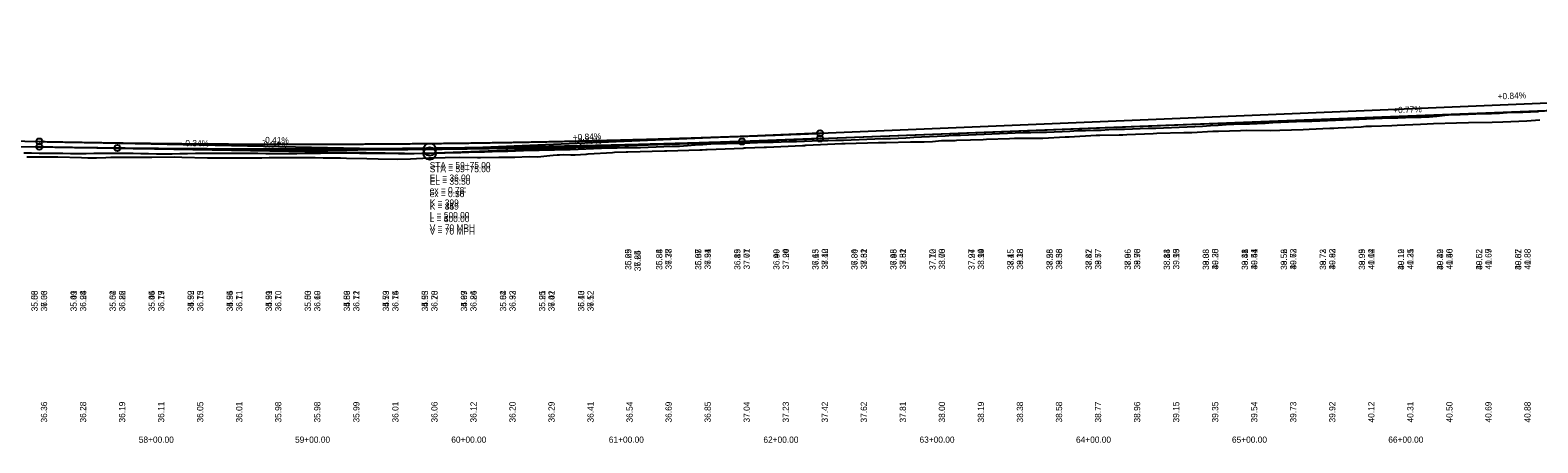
# Model space of a CAD drawing. Extents: x 3880794 to 3915434, y 287517 to 300173.
# Drawn here: x 3886257 to 3887223, y 296520 to 296784 of the extents above; entities that cross this region are included whole.
import ezdxf

# ---------------------------------------------------------------- set-up
doc = ezdxf.new("R2010")
doc.units = 0
for name, color, linetype in [('Level 1', 7, 'Continuous'), ('Level 2', 7, 'Continuous'), ('Level 30', 7, 'Continuous'), ('Level 31', 7, 'Continuous'), ('Level 32', 7, 'Continuous')]:
    doc.layers.add(name, color=color, linetype=linetype)

msp = doc.modelspace()

# ---------------------------------------------------------------- linework, layer by layer
at = {"layer": 'Level 1'}
for p, q in [((3886713.3, 296712.95), (3887288.3, 296735.06)), ((3886763.3, 296714.87), (3887238.3, 296733.14)), ((3885988.3, 296714.31), (3886263.3, 296709.57)), ((3886763.3, 296714.87), (3886517.29, 296705.41)), ((3886038.3, 296713.45), (3886313.3, 296708.71)), ((3886263.3, 296709.57), (3886509.3, 296705.33)), ((3886313.3, 296708.71), (3886509.3, 296705.33)), ((3886713.3, 296712.95), (3886517.29, 296705.41))]:
    msp.add_line(p, q, dxfattribs=at)
for points in [[(3886777.28, 296711.61), (3886777.93, 296711.63), (3886778.65, 296711.66), (3886779.46, 296711.74), (3886800.69, 296712.3), (3886801.5, 296712.33), (3886802.48, 296712.28), (3886803.73, 296712.3), (3886805.53, 296712.37), (3886821.22, 296712.7), (3886822.8, 296712.82), (3886825.32, 296712.79), (3886829.99, 296712.71), (3886835.19, 296712.96), (3886841.06, 296713.51), (3886849.7, 296713.65), (3886850.95, 296713.71), (3886859.58, 296713.97), (3886867.68, 296714.27), (3886869.92, 296714.35), (3886884.64, 296714.91), (3886887.72, 296715.02), (3886903.31, 296715.07), (3886905.9, 296715.12), (3886920.29, 296715.88), (3886922.81, 296715.99), (3886940.16, 296716.94), (3886942.47, 296717.06), (3886954.89, 296717.13), (3886957.16, 296717.29), (3886959.74, 296717.38), (3886976.66, 296718.15), (3886979.02, 296718.21), (3886996.27, 296718.61), (3886998.79, 296718.68), (3887001.42, 296718.78), (3887014.73, 296719.51), (3887018.4, 296719.56), (3887032.54, 296720.08), (3887036.17, 296720.18), (3887052.03, 296720.02), (3887057.62, 296720.16), (3887072.72, 296720.7), (3887076.51, 296720.83), (3887089.83, 296721.4), (3887092.35, 296721.47), (3887095.17, 296721.64), (3887109.82, 296722.45), (3887112.73, 296722.67), (3887116.46, 296722.73), (3887129.49, 296723.14), (3887132.79, 296723.46), (3887147.82, 296724.16), (3887151.97, 296724.25), (3887156.13, 296724.44), (3887170.81, 296724.98), (3887178.64, 296725.16), (3887193.73, 296725.44), (3887200.58, 296725.6), (3887215.89, 296726.2), (3887224.27, 296726.73)], [(3886255.33, 296703.2), (3886270.26, 296703.12), (3886275.11, 296703.11), (3886290.35, 296702.76), (3886294.42, 296702.54), (3886299.85, 296702.56), (3886305.8, 296702.58), (3886309.07, 296702.85), (3886325.47, 296702.92), (3886329.92, 296702.94), (3886335.28, 296702.94), (3886349.68, 296703.08), (3886354.67, 296702.88), (3886370.93, 296702.55), (3886374.88, 296702.38), (3886379.51, 296702.37), (3886385.58, 296702.39), (3886390.44, 296702.49), (3886405.74, 296702.53), (3886410.39, 296702.7), (3886415.81, 296702.69), (3886427.73, 296702.71), (3886429.52, 296702.73), (3886431.64, 296702.75), (3886440.03, 296702.76), (3886444.98, 296702.42), (3886456.07, 296702.48), (3886459.94, 296702.29), (3886472.94, 296701.96), (3886480.39, 296701.79), (3886492.93, 296701.69), (3886501.1, 296701.92), (3886512.68, 296702.37), (3886513.02, 296702.38), (3886523.13, 296702.71), (3886532.15, 296702.84), (3886543.81, 296702.62), (3886545.77, 296702.66), (3886557.62, 296702.96), (3886566.49, 296702.98), (3886567.81, 296702.98), (3886576.92, 296703.22), (3886582.57, 296703.2), (3886590.24, 296704.03), (3886592.33, 296704.23), (3886594.83, 296704.37), (3886596.34, 296704.45), (3886598.67, 296704.51), (3886603.66, 296704.35), (3886605.48, 296704.39), (3886606.51, 296704.46), (3886613.27, 296704.89), (3886613.64, 296704.92), (3886614.88, 296705.04), (3886630.41, 296705.95), (3886631.54, 296706), (3886639.06, 296706.24), (3886640.13, 296706.22), (3886663.57, 296706.99), (3886664.11, 296706.98), (3886664.61, 296706.98), (3886665.13, 296706.99), (3886686.28, 296707.62), (3886686.86, 296707.62), (3886687.68, 296707.63), (3886690.2, 296707.74), (3886691.01, 296707.78), (3886713.97, 296708.73), (3886714.72, 296708.79), (3886715.56, 296708.82), (3886727.4, 296709.35), (3886728.22, 296709.37), (3886729.06, 296709.36), (3886752.07, 296710.41), (3886752.6, 296710.44), (3886753.28, 296710.47), (3886753.85, 296710.5), (3886754.46, 296710.5), (3886777.28, 296711.61)]]:
    msp.add_lwpolyline(points, dxfattribs=at)
msp.add_circle((3886513.3, 296705.26), 4, dxfattribs=at)
msp.add_circle((3886513.3, 296705.26), 4, dxfattribs=at)
for points in [[(3886263.3, 296709.57), (3886273.3, 296709.4), (3886283.3, 296709.24), (3886293.3, 296709.1), (3886303.3, 296708.97), (3886313.3, 296708.84), (3886323.3, 296708.73), (3886333.3, 296708.63), (3886343.3, 296708.54), (3886353.3, 296708.47), (3886363.3, 296708.4), (3886373.3, 296708.34), (3886383.3, 296708.3), (3886393.3, 296708.27), (3886403.3, 296708.25), (3886413.3, 296708.23), (3886423.3, 296708.23), (3886433.3, 296708.25), (3886443.3, 296708.27), (3886453.3, 296708.3), (3886463.3, 296708.35), (3886473.3, 296708.4), (3886483.3, 296708.47), (3886493.3, 296708.55), (3886503.3, 296708.64), (3886513.3, 296708.74), (3886523.3, 296708.85), (3886533.3, 296708.97), (3886543.3, 296709.11), (3886553.3, 296709.25), (3886563.3, 296709.41), (3886573.3, 296709.58), (3886583.3, 296709.75), (3886593.3, 296709.94), (3886603.3, 296710.14), (3886613.3, 296710.36), (3886623.3, 296710.58), (3886633.3, 296710.81), (3886643.3, 296711.06), (3886653.3, 296711.32), (3886663.3, 296711.58), (3886673.3, 296711.86), (3886683.3, 296712.15), (3886693.3, 296712.45), (3886703.3, 296712.77), (3886713.3, 296713.09), (3886723.3, 296713.42), (3886733.3, 296713.77), (3886743.3, 296714.13), (3886753.3, 296714.49), (3886763.3, 296714.87)], [(3886313.3, 296708.71), (3886321.3, 296708.57), (3886329.3, 296708.45), (3886337.3, 296708.33), (3886345.3, 296708.22), (3886353.3, 296708.13), (3886361.3, 296708.04), (3886369.3, 296707.96), (3886377.3, 296707.89), (3886385.3, 296707.82), (3886393.3, 296707.77), (3886401.3, 296707.73), (3886409.3, 296707.69), (3886417.3, 296707.67), (3886425.3, 296707.65), (3886433.3, 296707.64), (3886441.3, 296707.64), (3886449.3, 296707.65), (3886457.3, 296707.67), (3886465.3, 296707.69), (3886473.3, 296707.73), (3886481.3, 296707.77), (3886489.3, 296707.83), (3886497.3, 296707.89), (3886505.3, 296707.96), (3886513.3, 296708.04), (3886521.3, 296708.13), (3886529.3, 296708.23), (3886537.3, 296708.34), (3886545.3, 296708.45), (3886553.3, 296708.58), (3886561.3, 296708.71), (3886569.3, 296708.85), (3886577.3, 296709.01), (3886585.3, 296709.17), (3886593.3, 296709.34), (3886601.3, 296709.52), (3886609.3, 296709.7), (3886617.3, 296709.9), (3886625.3, 296710.1), (3886633.3, 296710.32), (3886641.3, 296710.54), (3886649.3, 296710.77), (3886657.3, 296711.01), (3886665.3, 296711.26), (3886673.3, 296711.52), (3886681.3, 296711.79), (3886689.3, 296712.07), (3886697.3, 296712.35), (3886705.3, 296712.65), (3886713.3, 296712.95)]]:
    msp.add_spline(points, degree=3, dxfattribs=at)
at = {"layer": 'Level 2'}
for p, q in [((3886763.3, 296718.25), (3888338.3, 296784.36)), ((3885988.3, 296718.62), (3886263.3, 296712.93)), ((3886763.3, 296718.25), (3886517.29, 296707.92)), ((3886263.3, 296712.93), (3886509.3, 296707.84))]:
    msp.add_line(p, q, dxfattribs=at)
for points in [[(3886538.3, 296706.11), (3886543.3, 296706.24), (3886548.3, 296706.36), (3886553.3, 296706.49), (3886558.3, 296706.68), (3886563.3, 296706.84), (3886568.3, 296707.01), (3886573.3, 296707.18), (3886578.3, 296707.35), (3886583.3, 296707.4), (3886588.3, 296707.52), (3886593.3, 296707.65), (3886598.3, 296707.78), (3886603.3, 296707.91), (3886608.3, 296708.06), (3886613.3, 296708.26), (3886618.3, 296708.46), (3886623.3, 296708.66), (3886628.3, 296708.85), (3886633.3, 296708.94), (3886638.3, 296709.03), (3886643.3, 296709.11), (3886648.3, 296709.2), (3886653.3, 296709.29), (3886658.3, 296709.48), (3886663.3, 296709.67), (3886668.3, 296709.89), (3886673.3, 296709.87), (3886678.3, 296710.36), (3886683.3, 296710.79), (3886688.3, 296711.12), (3886693.3, 296711.47), (3886698.3, 296711.56), (3886703.3, 296711.68), (3886708.3, 296711.87), (3886713.3, 296711.98), (3886718.3, 296712.13), (3886723.3, 296712.3), (3886728.3, 296712.45), (3886733.3, 296712.59), (3886738.3, 296712.71), (3886743.3, 296712.84), (3886748.3, 296713.01), (3886753.3, 296713.19), (3886758.3, 296713.34), (3886763.3, 296713.48), (3886768.3, 296713.63), (3886773.3, 296713.74), (3886778.3, 296713.9), (3886783.3, 296714.09), (3886788.3, 296714.28), (3886793.3, 296714.49), (3886798.3, 296714.69), (3886803.3, 296714.83), (3886808.3, 296714.96), (3886813.3, 296715.16), (3886818.3, 296715.39), (3886823.3, 296715.62), (3886828.3, 296715.84), (3886833.3, 296716.06), (3886838.3, 296716.35), (3886843.3, 296716.63), (3886848.3, 296716.9), (3886853.3, 296717.11), (3886858.3, 296717.29), (3886863.3, 296717.46), (3886868.3, 296717.67), (3886873.3, 296717.9), (3886878.3, 296718.12), (3886883.3, 296718.35), (3886888.3, 296718.5), (3886893.3, 296718.64), (3886898.3, 296718.77), (3886903.3, 296718.88), (3886908.3, 296719), (3886913.3, 296719.13), (3886918.3, 296719.34), (3886923.3, 296719.61), (3886928.3, 296719.89), (3886933.3, 296720.01), (3886938.3, 296720.12), (3886943.3, 296720.29), (3886948.3, 296720.56), (3886953.3, 296720.75), (3886958.3, 296720.91), (3886963.3, 296721.08), (3886968.3, 296721.23), (3886973.3, 296721.39), (3886978.3, 296721.58), (3886983.3, 296721.76), (3886988.3, 296721.95), (3886993.3, 296722.16), (3886998.3, 296722.38), (3887003.3, 296722.6), (3887008.3, 296722.82), (3887013.3, 296723.14), (3887018.3, 296723.46), (3887023.3, 296723.78), (3887028.3, 296724.07), (3887033.3, 296724.18), (3887038.3, 296724.29)], [(3887038.3, 296724.29), (3887043.3, 296724.48), (3887048.3, 296724.7), (3887053.3, 296725.04), (3887058.3, 296725.39), (3887063.3, 296725.54), (3887068.3, 296725.7), (3887073.3, 296725.89), (3887078.3, 296726.07), (3887083.3, 296726.22), (3887088.3, 296726.39), (3887093.3, 296726.57), (3887098.3, 296726.79), (3887103.3, 296727.09), (3887108.3, 296727.3), (3887113.3, 296727.52), (3887118.3, 296727.71), (3887123.3, 296727.86), (3887128.3, 296728.03), (3887133.3, 296728.18), (3887138.3, 296728.38), (3887143.3, 296728.64), (3887148.3, 296728.64), (3887153.3, 296728.81), (3887158.3, 296729.27), (3887163.3, 296729.87), (3887168.3, 296730.17), (3887173.3, 296730.34), (3887178.3, 296730.52), (3887183.3, 296730.69), (3887188.3, 296730.84), (3887193.3, 296731), (3887198.3, 296731.16), (3887203.3, 296731.45), (3887208.3, 296731.65), (3887213.3, 296731.85), (3887218.3, 296732.04), (3887223.3, 296732.23)], [(3886253.3, 296705.64), (3886258.3, 296705.63), (3886263.3, 296705.52), (3886268.3, 296705.45), (3886273.3, 296705.44), (3886278.3, 296705.39), (3886283.3, 296705.26), (3886288.3, 296705.22), (3886293.3, 296705.3), (3886298.3, 296705.38), (3886303.3, 296705.36), (3886308.3, 296705.4), (3886313.3, 296705.45), (3886318.3, 296705.53), (3886323.3, 296705.5), (3886328.3, 296705.33), (3886333.3, 296705.16), (3886338.3, 296705.01), (3886343.3, 296705.05), (3886348.3, 296705.14), (3886353.3, 296705.22), (3886358.3, 296705.29), (3886363.3, 296705.37), (3886368.3, 296705.41), (3886373.3, 296705.46), (3886378.3, 296705.51), (3886383.3, 296705.53), (3886388.3, 296705.49), (3886393.3, 296705.44), (3886398.3, 296705.43), (3886403.3, 296705.4), (3886408.3, 296705.35), (3886413.3, 296705.3), (3886418.3, 296705.25), (3886423.3, 296705.24), (3886428.3, 296705.31), (3886433.3, 296705.39), (3886438.3, 296705.43), (3886443.3, 296705.5), (3886448.3, 296705.58), (3886453.3, 296705.65), (3886458.3, 296705.59), (3886463.3, 296705.58), (3886468.3, 296705.56), (3886473.3, 296705.55), (3886478.3, 296705.47), (3886483.3, 296705.42), (3886488.3, 296705.38), (3886493.3, 296705.35), (3886498.3, 296705.31), (3886503.3, 296705.34), (3886508.3, 296705.43), (3886513.3, 296705.53), (3886518.3, 296705.62), (3886523.3, 296705.71), (3886528.3, 296705.81), (3886533.3, 296705.99), (3886538.3, 296706.11)]]:
    msp.add_lwpolyline(points, dxfattribs=at)
for centre, radius in [((3886263.3, 296712.93), 2), ((3886763.3, 296718.25), 2), ((3886513.3, 296707.76), 4)]:
    msp.add_circle(centre, radius, dxfattribs=at)
msp.add_spline([(3886263.3, 296712.93), (3886273.3, 296712.73), (3886283.3, 296712.54), (3886293.3, 296712.37), (3886303.3, 296712.2), (3886313.3, 296712.05), (3886323.3, 296711.91), (3886333.3, 296711.79), (3886343.3, 296711.68), (3886353.3, 296711.57), (3886363.3, 296711.49), (3886373.3, 296711.41), (3886383.3, 296711.35), (3886393.3, 296711.3), (3886403.3, 296711.26), (3886413.3, 296711.24), (3886423.3, 296711.22), (3886433.3, 296711.22), (3886443.3, 296711.24), (3886453.3, 296711.26), (3886463.3, 296711.3), (3886473.3, 296711.35), (3886483.3, 296711.41), (3886493.3, 296711.49), (3886503.3, 296711.57), (3886513.3, 296711.67), (3886523.3, 296711.79), (3886533.3, 296711.91), (3886543.3, 296712.05), (3886553.3, 296712.2), (3886563.3, 296712.36), (3886573.3, 296712.54), (3886583.3, 296712.73), (3886593.3, 296712.93), (3886603.3, 296713.14), (3886613.3, 296713.36), (3886623.3, 296713.6), (3886633.3, 296713.85), (3886643.3, 296714.12), (3886653.3, 296714.39), (3886663.3, 296714.68), (3886673.3, 296714.98), (3886683.3, 296715.29), (3886693.3, 296715.62), (3886703.3, 296715.96), (3886713.3, 296716.31), (3886723.3, 296716.67), (3886733.3, 296717.05), (3886743.3, 296717.44), (3886753.3, 296717.84), (3886763.3, 296718.25)], degree=3, dxfattribs=at)
at = {"layer": 'Level 31'}
for centre in [(3886713.3, 296712.95), (3886763.3, 296714.87), (3886263.3, 296709.57), (3886313.3, 296708.71)]:
    msp.add_circle(centre, 2, dxfattribs=at)

# ---------------------------------------------------------------- texts
at = {"layer": 'Level 2'}
for s, rotation, p in [('+0.84%', 2.4036, (3887197.28, 296739.86)), ('-0.41%', 358.81474, (3886406.09, 296711.98)), ('+0.84%', 2.4036, (3886604.98, 296713.61)), ('37.25', 90, (3886648.45, 296629.75)), ('37.38', 90, (3886668.3, 296630.87)), ('37.54', 90, (3886693.3, 296630.87)), ('37.71', 90, (3886718.3, 296630.87)), ('37.90', 90, (3886743.3, 296630.87)), ('38.10', 90, (3886768.3, 296630.87)), ('38.31', 90, (3886793.3, 296630.87)), ('38.52', 90, (3886818.3, 296630.87)), ('38.73', 90, (3886843.3, 296630.87)), ('38.94', 90, (3886868.3, 296630.87)), ('39.15', 90, (3886893.3, 296630.87)), ('39.36', 90, (3886918.3, 296630.87)), ('39.57', 90, (3886943.3, 296630.87)), ('39.78', 90, (3886968.3, 296630.87)), ('39.99', 90, (3886993.3, 296630.87)), ('40.20', 90, (3887018.3, 296630.87)), ('40.41', 90, (3887043.3, 296630.87)), ('40.62', 90, (3887068.3, 296630.87)), ('40.83', 90, (3887093.3, 296630.87)), ('41.04', 90, (3887118.3, 296630.87)), ('41.25', 90, (3887143.3, 296630.87)), ('41.46', 90, (3887168.3, 296630.87)), ('41.67', 90, (3887193.3, 296630.87)), ('41.88', 90, (3887218.3, 296630.87)), ('37.03', 90, (3886268.3, 296604.02)), ('36.94', 90, (3886293.3, 296604.02)), ('36.86', 90, (3886318.3, 296604.02)), ('36.79', 90, (3886343.3, 296604.02)), ('36.75', 90, (3886368.3, 296604.02)), ('36.71', 90, (3886393.3, 296604.02)), ('36.70', 90, (3886418.3, 296604.02)), ('36.69', 90, (3886443.3, 296604.02)), ('36.71', 90, (3886468.3, 296604.02)), ('36.74', 90, (3886493.3, 296604.02)), ('36.78', 90, (3886518.3, 296604.02)), ('36.84', 90, (3886543.3, 296604.02)), ('36.92', 90, (3886568.3, 296604.02)), ('37.01', 90, (3886593.3, 296604.02)), ('37.12', 90, (3886618.3, 296604.02))]:
    msp.add_text(s, height=4, rotation=rotation, dxfattribs=at).set_placement(p)
for s, p in [('STA = 59+75.00', (3886513.3, 296695.76)), ('EL = 36.00', (3886513.3, 296687.76)), ("ex = 0.78'", (3886513.3, 296679.76)), ('K = 399', (3886513.3, 296671.76)), ('L = 500.00', (3886513.3, 296663.76)), ('V = 70 MPH', (3886513.3, 296655.76)), ('58+00.00', (3886326.99, 296519.76)), ('59+00.00', (3886427.05, 296519.76)), ('60+00.00', (3886527.12, 296519.76)), ('61+00.00', (3886628, 296519.76)), ('62+00.00', (3886726.99, 296519.76)), ('63+00.00', (3886826.96, 296519.76)), ('64+00.00', (3886927.18, 296519.76)), ('65+00.00', (3887027.05, 296519.76)), ('66+00.00', (3887127.18, 296519.76))]:
    msp.add_text(s, height=4, dxfattribs=at).set_placement(p)
at = {"layer": 'Level 30'}
for s, p in [('35.69', (3886642.45, 296630.63)), ('35.84', (3886662.3, 296630.63)), ('35.98', (3886687.3, 296630.63)), ('36.19', (3886712.3, 296630.63)), ('36.40', (3886737.3, 296630.63)), ('36.63', (3886762.3, 296630.63)), ('36.84', (3886787.3, 296630.63)), ('36.95', (3886812.3, 296630.63)), ('37.10', (3886837.3, 296630.63)), ('37.27', (3886862.3, 296630.63)), ('37.45', (3886887.3, 296630.63)), ('37.55', (3886912.3, 296630.63)), ('37.82', (3886937.3, 296630.63)), ('37.96', (3886962.3, 296630.63)), ('38.13', (3886987.3, 296630.63)), ('38.33', (3887012.3, 296630.63)), ('38.48', (3887037.3, 296630.63)), ('38.52', (3887062.3, 296630.63)), ('38.72', (3887087.3, 296630.63)), ('38.99', (3887112.3, 296630.63)), ('39.19', (3887137.3, 296630.63)), ('39.39', (3887162.3, 296630.63)), ('39.52', (3887187.3, 296630.63)), ('39.67', (3887212.3, 296630.63)), ('35.08', (3886262.25, 296604.02)), ('35.01', (3886287.25, 296604.02)), ('35.02', (3886312.25, 296604.02)), ('35.04', (3886337.25, 296604.02)), ('34.99', (3886362.25, 296604.02)), ('34.94', (3886387.25, 296604.02)), ('34.99', (3886412.25, 296604.02)), ('35.00', (3886437.25, 296604.02)), ('34.89', (3886462.25, 296604.02)), ('34.79', (3886487.25, 296604.02)), ('34.93', (3886512.25, 296604.02)), ('34.99', (3886537.25, 296604.02)), ('35.04', (3886562.25, 296604.02)), ('35.21', (3886587.25, 296604.02)), ('35.43', (3886612.25, 296604.02))]:
    msp.add_text(s, height=4, rotation=90, dxfattribs=at).set_placement(p)
for s, p in [('58+00.00', (3886326.99, 296519.76)), ('58+00.00', (3886326.99, 296519.76)), ('58+00.00', (3886326.99, 296519.76)), ('59+00.00', (3886427.05, 296519.76)), ('59+00.00', (3886427.05, 296519.76)), ('59+00.00', (3886427.05, 296519.76)), ('60+00.00', (3886527.12, 296519.76)), ('60+00.00', (3886527.12, 296519.76)), ('60+00.00', (3886527.12, 296519.76)), ('61+00.00', (3886628, 296519.76)), ('61+00.00', (3886628, 296519.76)), ('61+00.00', (3886628, 296519.76)), ('62+00.00', (3886726.99, 296519.76)), ('62+00.00', (3886726.99, 296519.76)), ('62+00.00', (3886726.99, 296519.76)), ('63+00.00', (3886826.96, 296519.76)), ('63+00.00', (3886826.96, 296519.76)), ('63+00.00', (3886826.96, 296519.76)), ('64+00.00', (3886927.18, 296519.76)), ('64+00.00', (3886927.18, 296519.76)), ('64+00.00', (3886927.18, 296519.76)), ('65+00.00', (3887027.05, 296519.76)), ('65+00.00', (3887027.05, 296519.76)), ('65+00.00', (3887027.05, 296519.76)), ('66+00.00', (3887127.18, 296519.76)), ('66+00.00', (3887127.18, 296519.76)), ('66+00.00', (3887127.18, 296519.76))]:
    msp.add_text(s, height=4, dxfattribs=at).set_placement(p)
at = {"layer": 'Level 31'}
for s, rotation, p in [('+0.77%', 2.2026, (3887130.39, 296730.99)), ('+0.77%', 2.2026, (3886605.25, 296710.8)), ('+0.77%', 2.2026, (3886605.25, 296710.8)), ('-0.34%', 359.01224, (3886355, 296709.99)), ('-0.34%', 359.01224, (3886405.03, 296709.12)), ('-0.34%', 359.01224, (3886405.03, 296709.12)), ('36.64', 90, (3886648.45, 296629.75)), ('36.77', 90, (3886668.3, 296630.87)), ('36.91', 90, (3886693.3, 296630.87)), ('37.07', 90, (3886718.3, 296630.87)), ('37.24', 90, (3886743.3, 296630.87)), ('37.42', 90, (3886768.3, 296630.87)), ('37.62', 90, (3886793.3, 296630.87)), ('37.81', 90, (3886818.3, 296630.87)), ('38.00', 90, (3886843.3, 296630.87)), ('38.19', 90, (3886868.3, 296630.87)), ('38.38', 90, (3886893.3, 296630.87)), ('38.58', 90, (3886918.3, 296630.87)), ('38.77', 90, (3886943.3, 296630.87)), ('38.96', 90, (3886968.3, 296630.87)), ('39.15', 90, (3886993.3, 296630.87)), ('39.35', 90, (3887018.3, 296630.87)), ('39.54', 90, (3887043.3, 296630.87)), ('39.73', 90, (3887068.3, 296630.87)), ('39.92', 90, (3887093.3, 296630.87)), ('40.12', 90, (3887118.3, 296630.87)), ('40.31', 90, (3887143.3, 296630.87)), ('40.50', 90, (3887168.3, 296630.87)), ('40.69', 90, (3887193.3, 296630.87)), ('40.88', 90, (3887218.3, 296630.87)), ('36.36', 90, (3886268.3, 296604.02)), ('36.28', 90, (3886293.3, 296604.02)), ('36.22', 90, (3886318.3, 296604.02)), ('36.17', 90, (3886343.3, 296604.02)), ('36.13', 90, (3886368.3, 296604.02)), ('36.11', 90, (3886393.3, 296604.02)), ('36.10', 90, (3886418.3, 296604.02)), ('36.10', 90, (3886443.3, 296604.02)), ('36.12', 90, (3886468.3, 296604.02)), ('36.15', 90, (3886493.3, 296604.02)), ('36.20', 90, (3886518.3, 296604.02)), ('36.26', 90, (3886543.3, 296604.02)), ('36.33', 90, (3886568.3, 296604.02)), ('36.42', 90, (3886593.3, 296604.02)), ('36.52', 90, (3886618.3, 296604.02)), ('36.36', 90, (3886268.3, 296532.76)), ('36.28', 90, (3886293.3, 296532.76)), ('36.19', 90, (3886318.3, 296532.76)), ('36.11', 90, (3886343.3, 296532.76)), ('36.05', 90, (3886368.3, 296532.76)), ('36.01', 90, (3886393.3, 296532.76)), ('35.98', 90, (3886418.3, 296532.76)), ('35.98', 90, (3886443.3, 296532.76)), ('35.99', 90, (3886468.3, 296532.76)), ('36.01', 90, (3886493.3, 296532.76)), ('36.06', 90, (3886518.3, 296532.76)), ('36.12', 90, (3886543.3, 296532.76)), ('36.20', 90, (3886568.3, 296532.76)), ('36.29', 90, (3886593.3, 296532.76)), ('36.41', 90, (3886618.3, 296532.76)), ('36.54', 90, (3886643.3, 296532.76)), ('36.69', 90, (3886668.3, 296532.76)), ('36.85', 90, (3886693.3, 296532.76)), ('37.04', 90, (3886718.3, 296532.76)), ('37.23', 90, (3886743.3, 296532.76)), ('37.42', 90, (3886768.3, 296532.76)), ('37.62', 90, (3886793.3, 296532.76)), ('37.81', 90, (3886818.3, 296532.76)), ('38.00', 90, (3886843.3, 296532.76)), ('38.19', 90, (3886868.3, 296532.76)), ('38.38', 90, (3886893.3, 296532.76)), ('38.58', 90, (3886918.3, 296532.76)), ('38.77', 90, (3886943.3, 296532.76)), ('38.96', 90, (3886968.3, 296532.76)), ('39.15', 90, (3886993.3, 296532.76)), ('39.35', 90, (3887018.3, 296532.76)), ('39.54', 90, (3887043.3, 296532.76)), ('39.73', 90, (3887068.3, 296532.76)), ('39.92', 90, (3887093.3, 296532.76)), ('40.12', 90, (3887118.3, 296532.76)), ('40.31', 90, (3887143.3, 296532.76)), ('40.50', 90, (3887168.3, 296532.76)), ('40.69', 90, (3887193.3, 296532.76)), ('40.88', 90, (3887218.3, 296532.76))]:
    msp.add_text(s, height=4, rotation=rotation, dxfattribs=at).set_placement(p)
for s, p in [('STA = 59+75.00', (3886513.3, 296693.26)), ('STA = 59+75.00', (3886513.3, 296693.26)), ('EL = 35.50', (3886513.3, 296685.26)), ('EL = 35.50', (3886513.3, 296685.26)), ("ex = 0.70'", (3886513.3, 296677.26)), ("ex = 0.56'", (3886513.3, 296677.26)), ('K = 449', (3886513.3, 296669.26)), ('K = 359', (3886513.3, 296669.26)), ('V = 70 MPH', (3886513.3, 296653.26)), ('L = 500.00', (3886513.3, 296661.26)), ('L = 400.00', (3886513.3, 296661.26))]:
    msp.add_text(s, height=4, dxfattribs=at).set_placement(p)
at = {"layer": 'Level 32'}
for s, p in [('36.25', (3886642.45, 296630.63)), ('36.38', (3886662.3, 296630.63)), ('36.67', (3886687.3, 296630.63)), ('36.85', (3886712.3, 296630.63)), ('36.99', (3886737.3, 296630.63)), ('37.15', (3886762.3, 296630.63)), ('37.30', (3886787.3, 296630.63)), ('37.48', (3886812.3, 296630.63)), ('37.72', (3886837.3, 296630.63)), ('37.94', (3886862.3, 296630.63)), ('38.15', (3886887.3, 296630.63)), ('38.28', (3886912.3, 296630.63)), ('38.47', (3886937.3, 296630.63)), ('38.66', (3886962.3, 296630.63)), ('38.84', (3886987.3, 296630.63)), ('39.08', (3887012.3, 296630.63)), ('39.31', (3887037.3, 296630.63)), ('39.56', (3887062.3, 296630.63)), ('39.73', (3887087.3, 296630.63)), ('39.95', (3887112.3, 296630.63)), ('40.12', (3887137.3, 296630.63)), ('40.42', (3887162.3, 296630.63)), ('40.62', (3887187.3, 296630.63)), ('40.82', (3887212.3, 296630.63)), ('35.55', (3886262.25, 296604.02)), ('35.49', (3886287.25, 296604.02)), ('35.54', (3886312.25, 296604.02)), ('35.45', (3886337.25, 296604.02)), ('35.52', (3886362.25, 296604.02)), ('35.55', (3886387.25, 296604.02)), ('35.51', (3886412.25, 296604.02)), ('35.53', (3886437.25, 296604.02)), ('35.56', (3886462.25, 296604.02)), ('35.53', (3886487.25, 296604.02)), ('35.55', (3886512.25, 296604.02)), ('35.67', (3886537.25, 296604.02)), ('35.82', (3886562.25, 296604.02)), ('35.95', (3886587.25, 296604.02)), ('36.10', (3886612.25, 296604.02))]:
    msp.add_text(s, height=4, rotation=90, dxfattribs=at).set_placement(p)

doc.saveas('drawing.dxf')
